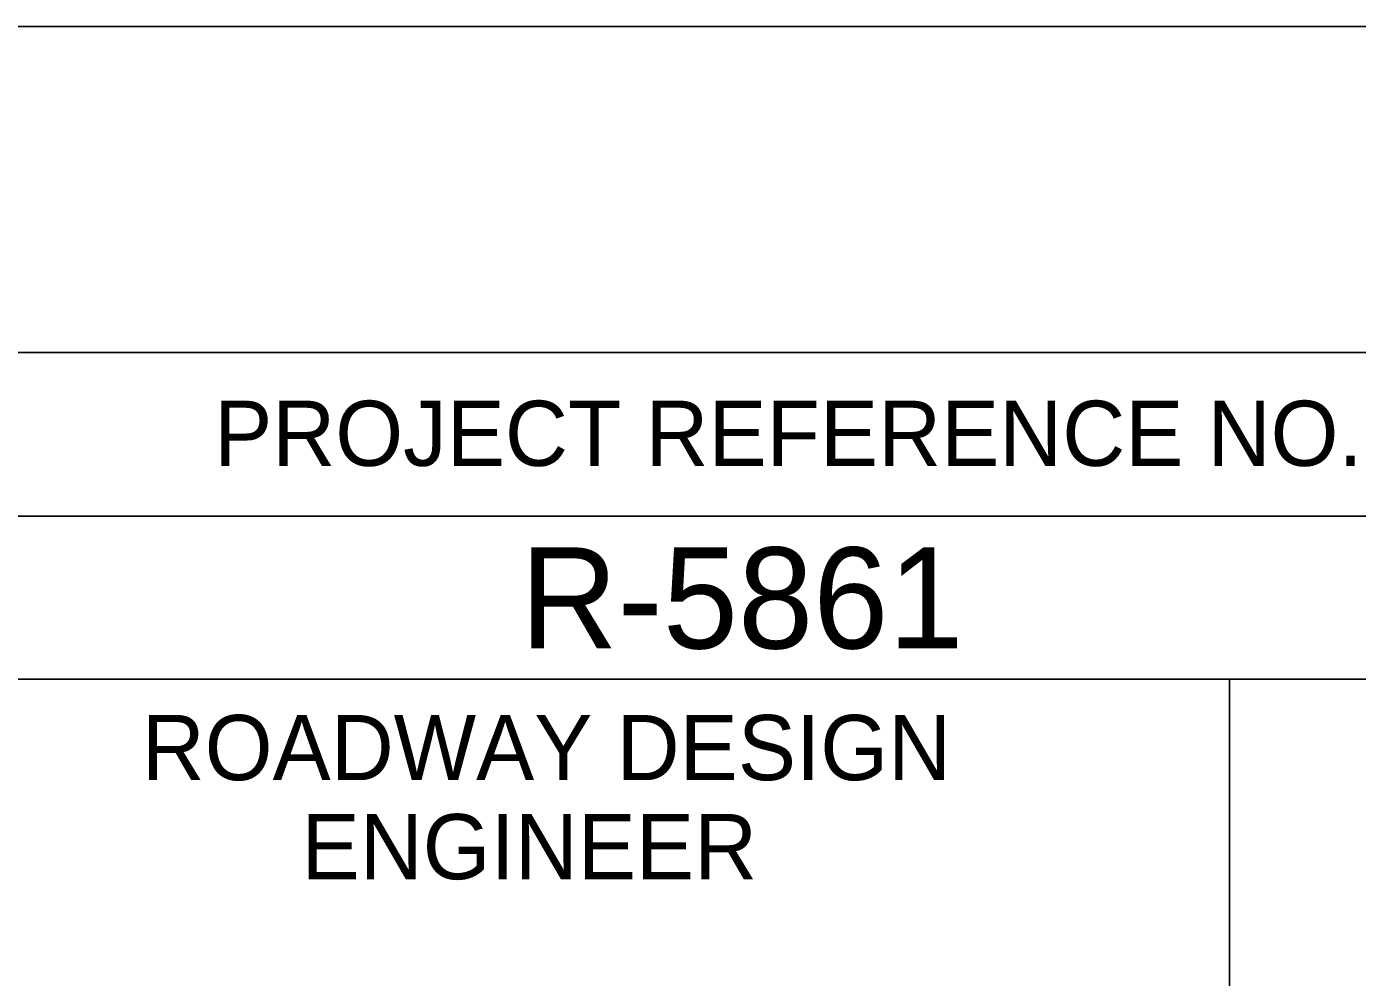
# Model space of a CAD drawing. Extents: x 502400 to 509344, y 448070 to 484209.
# Drawn here: x 507076.9 to 507178.9, y 484135.8 to 484208.7 of the extents above; entities that cross this region are included whole.
import ezdxf

# ---------------------------------------------------------------- set-up
doc = ezdxf.new("R2010")
doc.units = 0
for name, color, linetype in [('Sheet Data Field CELL', 7, 'Continuous'), ('Sheet Plot Border Outside CELL', 7, 'Continuous'), ('Sheet Profile CELL', 7, 'Continuous'), ('Sheet Profile Grid Major CELL', 7, 'Continuous')]:
    doc.layers.add(name, color=color, linetype=linetype)

msp = doc.modelspace()

# ---------------------------------------------------------------- linework, layer by layer
at = {"layer": 'Sheet Plot Border Outside CELL'}
msp.add_lwpolyline([(505602.08, 483108.71), (507286.08, 483108.71), (507286.08, 484208.71), (505602.08, 484208.71)], close=True, dxfattribs=at)
at = {"layer": 'Sheet Profile CELL'}
for p, q in [((507069.03, 484171.16), (507269.08, 484171.16)), ((507169.08, 484158.66), (507169.08, 484046.21))]:
    msp.add_line(p, q, dxfattribs=at)
for points in [[(507269.08, 484183.71), (505769.08, 484183.71), (505769.08, 483133.71), (507269.08, 483133.71)], [(507069.03, 484183.71), (507269.08, 484183.71), (507269.08, 484158.66), (507069.03, 484158.66)], [(507069.03, 484158.66), (507169.08, 484158.66), (507169.08, 484046.16), (507069.03, 484046.16)], [(507169.08, 484158.66), (507269.08, 484158.66), (507269.08, 484046.16), (507169.08, 484046.16)]]:
    msp.add_lwpolyline(points, close=True, dxfattribs=at)
at = {"layer": 'Sheet Profile Grid Major CELL'}
msp.add_lwpolyline([(506519.08, 483683.71), (506569.08, 483683.71), (506569.08, 484183.71), (506619.08, 484183.71), (506619.08, 483683.71), (506669.08, 483683.71), (506669.08, 484183.71), (506719.08, 484183.71), (506719.08, 483683.71), (506769.08, 483683.71), (506769.08, 484183.71), (506819.08, 484183.71), (506819.08, 483683.71), (506869.08, 483683.71), (506869.08, 484183.71), (506919.08, 484183.71), (506919.08, 483683.71), (506969.08, 483683.71), (506969.08, 484183.71), (507019.08, 484183.71), (507019.08, 483683.71), (507069.08, 483683.71), (507069.08, 484183.71), (507095.38, 484183.71)], dxfattribs=at)

# ---------------------------------------------------------------- texts
at = {"layer": 'Sheet Data Field CELL'}
msp.add_text('R-5861', height=7.75, dxfattribs=at).set_placement((507114.7, 484161.02))
at = {"layer": 'Sheet Profile CELL'}
for s, height, p in [('PROJECT REFERENCE NO.', 5.0001, (507091.24, 484175.02)), ('ROADWAY DESIGN', 5.0001, (507085.69, 484150.92)), ('ENGINEER', 5, (507097.94, 484143.32))]:
    msp.add_text(s, height=height, dxfattribs=at).set_placement(p)

doc.saveas('drawing.dxf')
